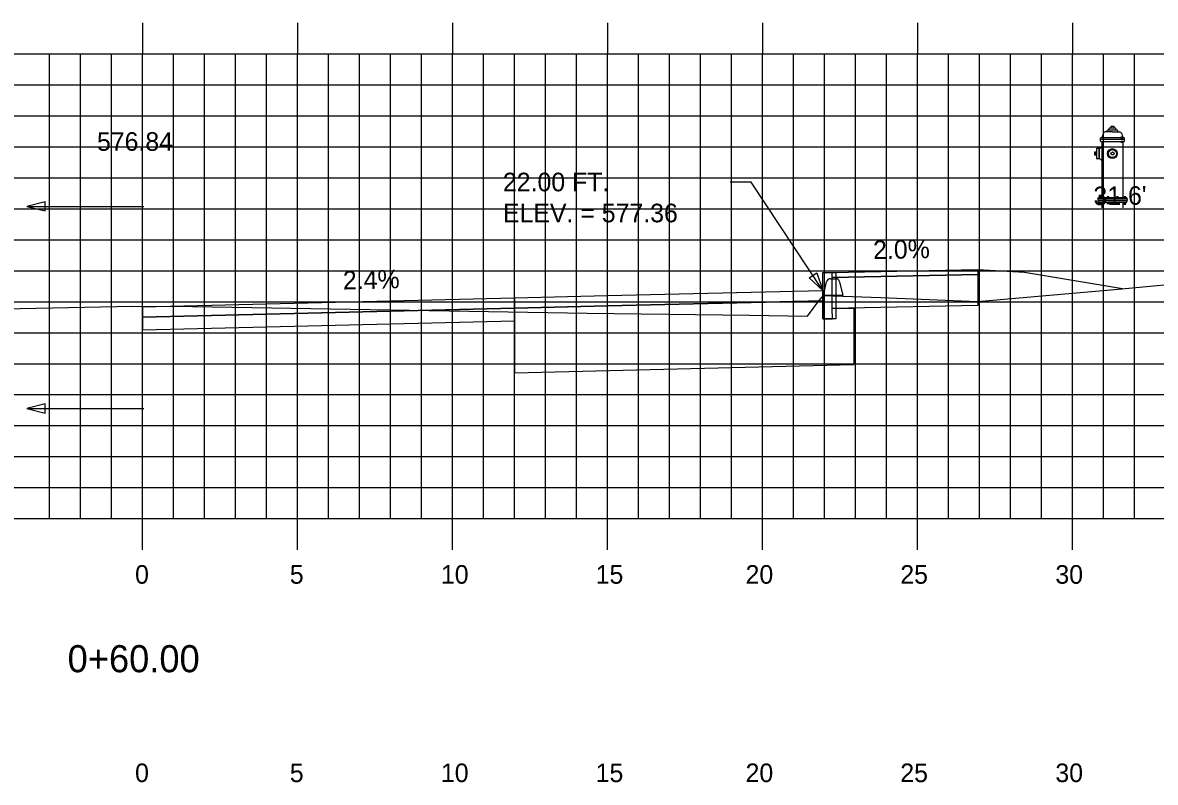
# Model space of a CAD drawing. Extents: x 1048343 to 1048513, y 781387 to 781497.
# Drawn here: x 1048422.25 to 1048458.79, y 781417.87 to 781442.38 of the extents above; entities that cross this region are included whole.
import ezdxf

# ---------------------------------------------------------------- set-up
doc = ezdxf.new("R2010")
doc.units = 0
for name, color, linetype in [('ANNOTATION', 7, 'Continuous'), ('D_Curb_Type1_Lt', 7, 'Continuous'), ('D_Roadway_Berm', 7, 'Continuous'), ('D_Roadway_Centerline', 7, 'Continuous'), ('D_Roadway_Centerline_Text', 7, 'Continuous'), ('D_Roadway_Edge_Shoulder', 7, 'Continuous'), ('D_Roadway_Edge_TW', 7, 'Continuous'), ('D_Roadway_Pavement', 7, 'Continuous'), ('D_Roadway_Sidewalks_Paved', 7, 'Continuous'), ('D_Roadway_SlopeLines', 7, 'Continuous'), ('D_Roadway_SubGrade', 7, 'Continuous'), ('D_Text_Standard', 7, 'Continuous'), ('H_V ANNOTATION', 7, 'Continuous'), ('MAJOR', 7, 'Continuous'), ('MINOR', 7, 'Continuous'), ('S_Curb_Type_3', 7, 'Continuous'), ('S_Roadway_Centerline', 7, 'Continuous'), ('S_Utilities_Hydrant', 7, 'Continuous')]:
    doc.layers.add(name, color=color, linetype=linetype)

msp = doc.modelspace()

# ---------------------------------------------------------------- linework, layer by layer
at = {"layer": 'ANNOTATION'}
for p, q in [((1048422.382, 781436.451), (1048426.157, 781436.451)), ((1048422.382, 781429.933), (1048426.157, 781429.933))]:
    msp.add_line(p, q, dxfattribs=at)
for points in [[(1048422.982, 781436.601), (1048422.382, 781436.451), (1048422.982, 781436.301)], [(1048422.982, 781430.083), (1048422.382, 781429.933), (1048422.982, 781429.783)]]:
    msp.add_lwpolyline(points, close=True, dxfattribs=at)
at = {"layer": 'D_Curb_Type1_Lt'}
msp.add_lwpolyline([(1048448.485, 781434.319), (1048448.485, 781432.819), (1048448.069, 781432.819), (1048448.069, 781434.319)], close=True, dxfattribs=at)
at = {"layer": 'D_Roadway_Berm'}
msp.add_lwpolyline([(1048453.069, 781434.413), (1048454.569, 781434.323)], dxfattribs=at)
at = {"layer": 'D_Roadway_Centerline'}
for p, q in [((1048426.119, 781429.933), (1048426.119, 781436.49)), ((1048426.119, 781433.211), (1048426.119, 781432.461))]:
    msp.add_line(p, q, dxfattribs=at)
at = {"layer": 'D_Roadway_Edge_Shoulder'}
msp.add_lwpolyline([(1048438.119, 781433.498), (1048441.119, 781433.57), (1048448.068, 781433.736), (1048448.068, 781433.403), (1048441.119, 781433.237), (1048438.119, 781433.165)], close=True, dxfattribs=at)
at = {"layer": 'D_Roadway_Edge_TW'}
msp.add_lwpolyline([(1048426.119, 781433.211), (1048438.119, 781433.498), (1048438.119, 781433.165), (1048426.119, 781432.878)], dxfattribs=at)
at = {"layer": 'D_Roadway_Pavement'}
msp.add_lwpolyline([(1048426.119, 781432.878), (1048438.119, 781433.165), (1048438.119, 781432.748), (1048426.119, 781432.461)], dxfattribs=at)
at = {"layer": 'D_Roadway_Sidewalks_Paved'}
msp.add_lwpolyline([(1048448.369, 781434.319), (1048453.069, 781434.413), (1048453.069, 781434.247), (1048448.369, 781434.153)], close=True, dxfattribs=at)
at = {"layer": 'D_Roadway_SlopeLines'}
msp.add_lwpolyline([(1048454.569, 781434.323), (1048457.73, 781433.796)], dxfattribs=at)
at = {"layer": 'D_Roadway_SubGrade'}
for p in [(1048449.068, 781433.167), (1048438.119, 781431.082)]:
    msp.add_line(p, (1048449.068, 781431.343), dxfattribs=at)
msp.add_lwpolyline([(1048448.369, 781434.153), (1048453.069, 781434.247), (1048453.069, 781433.247), (1048448.369, 781433.153)], close=True, dxfattribs=at)
for points in [[(1048438.119, 781431.301), (1048438.119, 781433.165), (1048438.119, 781433.165), (1048441.119, 781433.237), (1048448.068, 781433.403), (1048448.068, 781432.819), (1048448.378, 781432.819), (1048448.369, 781433.153), (1048449.068, 781433.167), (1048449.068, 781431.562)], [(1048438.119, 781433.165), (1048438.119, 781431.082)]]:
    msp.add_lwpolyline(points, dxfattribs=at)
at = {"layer": 'D_Text_Standard'}
msp.add_lwpolyline([(1048448.068, 781433.736), (1048445.751, 781437.236), (1048445.071, 781437.236)], dxfattribs=at)
msp.add_lwpolyline([(1048448.068, 781433.736), (1048447.625, 781434.141), (1048447.868, 781434.302)], close=True, dxfattribs=at)
at = {"layer": 'MAJOR'}
for p, q in [((1048426.119, 781442.377), (1048426.119, 781441.375)), ((1048431.119, 781442.377), (1048431.119, 781441.375)), ((1048436.119, 781442.377), (1048436.119, 781441.375)), ((1048441.119, 781442.377), (1048441.119, 781441.375)), ((1048446.119, 781442.377), (1048446.119, 781441.375)), ((1048451.119, 781442.377), (1048451.119, 781441.375)), ((1048456.119, 781442.377), (1048456.119, 781441.375)), ((1048356.119, 781441.375), (1048496.119, 781441.375)), ((1048356.119, 781441.375), (1048496.119, 781441.375)), ((1048426.119, 781426.375), (1048426.119, 781441.375)), ((1048431.119, 781426.375), (1048431.119, 781441.375)), ((1048436.119, 781426.375), (1048436.119, 781441.375)), ((1048441.119, 781426.375), (1048441.119, 781441.375)), ((1048446.119, 781426.375), (1048446.119, 781441.375)), ((1048451.119, 781426.375), (1048451.119, 781441.375)), ((1048456.119, 781426.375), (1048456.119, 781441.375)), ((1048356.119, 781436.375), (1048496.119, 781436.375)), ((1048356.119, 781431.375), (1048496.119, 781431.375)), ((1048356.119, 781426.375), (1048496.119, 781426.375)), ((1048356.119, 781426.375), (1048496.119, 781426.375)), ((1048426.119, 781425.373), (1048426.119, 781426.375)), ((1048431.119, 781425.373), (1048431.119, 781426.375)), ((1048436.119, 781425.373), (1048436.119, 781426.375)), ((1048441.119, 781425.373), (1048441.119, 781426.375)), ((1048446.119, 781425.373), (1048446.119, 781426.375)), ((1048451.119, 781425.373), (1048451.119, 781426.375)), ((1048456.119, 781425.373), (1048456.119, 781426.375))]:
    msp.add_line(p, q, dxfattribs=at)
at = {"layer": 'MINOR'}
for p, q in [((1048423.119, 781426.375), (1048423.119, 781441.375)), ((1048424.119, 781426.375), (1048424.119, 781441.375)), ((1048425.119, 781426.375), (1048425.119, 781441.375)), ((1048427.119, 781426.375), (1048427.119, 781441.375)), ((1048428.119, 781426.375), (1048428.119, 781441.375)), ((1048429.119, 781426.375), (1048429.119, 781441.375)), ((1048430.119, 781426.375), (1048430.119, 781441.375)), ((1048432.119, 781426.375), (1048432.119, 781441.375)), ((1048433.119, 781426.375), (1048433.119, 781441.375)), ((1048434.119, 781426.375), (1048434.119, 781441.375)), ((1048435.119, 781426.375), (1048435.119, 781441.375)), ((1048437.119, 781426.375), (1048437.119, 781441.375)), ((1048438.119, 781426.375), (1048438.119, 781441.375)), ((1048439.119, 781426.375), (1048439.119, 781441.375)), ((1048440.119, 781426.375), (1048440.119, 781441.375)), ((1048442.119, 781426.375), (1048442.119, 781441.375)), ((1048443.119, 781426.375), (1048443.119, 781441.375)), ((1048444.119, 781426.375), (1048444.119, 781441.375)), ((1048445.119, 781426.375), (1048445.119, 781441.375)), ((1048447.119, 781426.375), (1048447.119, 781441.375)), ((1048448.119, 781426.375), (1048448.119, 781441.375)), ((1048449.119, 781426.375), (1048449.119, 781441.375)), ((1048450.119, 781426.375), (1048450.119, 781441.375)), ((1048452.119, 781426.375), (1048452.119, 781441.375)), ((1048453.119, 781426.375), (1048453.119, 781441.375)), ((1048454.119, 781426.375), (1048454.119, 781441.375)), ((1048455.119, 781426.375), (1048455.119, 781441.375)), ((1048457.119, 781426.375), (1048457.119, 781441.375)), ((1048458.119, 781426.375), (1048458.119, 781441.375)), ((1048356.119, 781440.375), (1048496.119, 781440.375)), ((1048356.119, 781439.375), (1048496.119, 781439.375)), ((1048356.119, 781438.375), (1048496.119, 781438.375)), ((1048356.119, 781437.375), (1048496.119, 781437.375)), ((1048356.119, 781435.375), (1048496.119, 781435.375)), ((1048356.119, 781434.375), (1048496.119, 781434.375)), ((1048356.119, 781433.375), (1048496.119, 781433.375)), ((1048356.119, 781432.375), (1048496.119, 781432.375)), ((1048356.119, 781430.375), (1048496.119, 781430.375)), ((1048356.119, 781429.375), (1048496.119, 781429.375)), ((1048356.119, 781428.375), (1048496.119, 781428.375)), ((1048356.119, 781427.375), (1048496.119, 781427.375))]:
    msp.add_line(p, q, dxfattribs=at)
at = {"layer": 'S_Curb_Type_3'}
for points in [[(1048448.606, 781434.02), (1048448.709, 781433.576), (1048448.084, 781433.576), (1048448.186, 781434.02)], [(1048448.308, 781434.117), (1048448.484, 781434.117)]]:
    msp.add_lwpolyline(points, dxfattribs=at)
for centre, start, end in [((1048448.308, 781433.992), 90, 167.0054), ((1048448.484, 781433.992), 12.9946, 90)]:
    msp.add_arc(centre, 0.125, start, end, dxfattribs=at)
at = {"layer": 'S_Roadway_Centerline'}
msp.add_lwpolyline([(1048397.517, 781432.883), (1048403.278, 781432.868), (1048405.917, 781432.863), (1048409.959, 781432.912), (1048412.069, 781432.919), (1048412.094, 781432.924), (1048422.166, 781433.153), (1048425.802, 781433.232), (1048427.73, 781433.216), (1048440.46, 781433.006), (1048445.704, 781432.939), (1048447.573, 781432.913), (1048447.942, 781433.407), (1048448.084, 781433.576), (1048449.937, 781433.508), (1048453.059, 781433.386), (1048457.596, 781433.784), (1048467.65, 781434.721), (1048470.236, 781434.963), (1048489.197, 781435.231), (1048493.877, 781435.266), (1048494.113, 781435.27), (1048495.01, 781435.311), (1048496.119, 781435.359)], dxfattribs=at)
at = {"layer": 'S_Utilities_Hydrant'}
for p, q in [((1048457.109, 781438.789), (1048457.07, 781438.661)), ((1048457.408, 781438.86), (1048457.177, 781438.86)), ((1048457.255, 781438.916), (1048457.56, 781438.916)), ((1048457.295, 781438.957), (1048457.295, 781438.916)), ((1048457.504, 781438.972), (1048457.312, 781438.972)), ((1048457.408, 781438.86), (1048457.639, 781438.86)), ((1048457.52, 781438.916), (1048457.52, 781438.957)), ((1048457.707, 781438.789), (1048457.746, 781438.661)), ((1048457.014, 781438.645), (1048457.014, 781438.564)), ((1048457.803, 781438.604), (1048457.014, 781438.604)), ((1048457.786, 781438.661), (1048457.03, 781438.661)), ((1048457.07, 781438.548), (1048457.07, 781436.741)), ((1048457.07, 781438.39), (1048457.07, 781438.39)), ((1048457.089, 781438.661), (1048457.089, 781438.678)), ((1048457.089, 781438.524), (1048457.089, 781438.548)), ((1048457.118, 781438.678), (1048457.118, 781438.661)), ((1048457.118, 781438.548), (1048457.118, 781438.524)), ((1048457.699, 781438.678), (1048457.699, 781438.661)), ((1048457.699, 781438.548), (1048457.699, 781438.524)), ((1048457.727, 781438.661), (1048457.727, 781438.678)), ((1048457.727, 781438.524), (1048457.727, 781438.548)), ((1048457.746, 781438.548), (1048457.746, 781436.741)), ((1048456.867, 781438.201), (1048456.867, 781438.199)), ((1048456.867, 781438.199), (1048456.867, 781438.109)), ((1048456.867, 781438.106), (1048456.867, 781438.109)), ((1048456.877, 781438.214), (1048456.877, 781438.093)), ((1048456.882, 781438.215), (1048456.882, 781438.093)), ((1048456.902, 781438.221), (1048456.894, 781438.22)), ((1048456.902, 781438.086), (1048456.894, 781438.088)), ((1048456.902, 781437.996), (1048456.902, 781438.313)), ((1048456.918, 781438.328), (1048456.979, 781438.328)), ((1048456.979, 781438.328), (1048456.979, 781437.979)), ((1048456.986, 781438.318), (1048456.979, 781438.318)), ((1048456.986, 781437.985), (1048456.986, 781438.323)), ((1048456.979, 781437.979), (1048456.917, 781437.979)), ((1048456.986, 781437.99), (1048456.979, 781437.99)), ((1048457.07, 781437.918), (1048457.07, 781437.918)), ((1048457.889, 781436.685), (1048456.938, 781436.685)), ((1048457.889, 781436.629), (1048456.938, 781436.629)), ((1048456.963, 781436.741), (1048457.864, 781436.741)), ((1048457.864, 781436.572), (1048456.963, 781436.572)), ((1048456.998, 781436.759), (1048456.998, 781436.741)), ((1048456.998, 781436.572), (1048456.998, 781436.548)), ((1048457.026, 781436.741), (1048457.026, 781436.759)), ((1048457.026, 781436.548), (1048457.026, 781436.572)), ((1048457.07, 781436.572), (1048457.07, 781436.405)), ((1048457.249, 781436.759), (1048457.249, 781436.741)), ((1048457.249, 781436.572), (1048457.249, 781436.548)), ((1048457.278, 781436.741), (1048457.278, 781436.759)), ((1048457.278, 781436.548), (1048457.278, 781436.572)), ((1048457.55, 781436.759), (1048457.55, 781436.741)), ((1048457.55, 781436.572), (1048457.55, 781436.548)), ((1048457.577, 781436.741), (1048457.577, 781436.759)), ((1048457.577, 781436.548), (1048457.577, 781436.572)), ((1048457.746, 781436.572), (1048457.746, 781436.405)), ((1048457.801, 781436.759), (1048457.801, 781436.741)), ((1048457.801, 781436.572), (1048457.801, 781436.548)), ((1048457.829, 781436.741), (1048457.829, 781436.759)), ((1048457.829, 781436.548), (1048457.829, 781436.572))]:
    msp.add_line(p, q, dxfattribs=at)
for points in [[(1048457.239, 781438.86), (1048457.239, 781438.901), (1048457.24, 781438.901), (1048457.239, 781438.901)], [(1048457.465, 781438.972), (1048457.465, 781439.028), (1048457.352, 781439.028), (1048457.352, 781438.972)], [(1048457.577, 781438.901), (1048457.576, 781438.901), (1048457.577, 781438.901), (1048457.577, 781438.86)], [(1048457.029, 781438.547), (1048457.029, 781438.548), (1048457.787, 781438.548), (1048457.787, 781438.547)], [(1048457.076, 781438.661), (1048457.076, 781438.678), (1048457.079, 781438.682), (1048457.128, 781438.682), (1048457.131, 781438.678), (1048457.131, 781438.661), (1048457.076, 781438.661)], [(1048457.131, 781438.548), (1048457.131, 781438.524), (1048457.128, 781438.52), (1048457.079, 781438.52), (1048457.076, 781438.524), (1048457.076, 781438.548), (1048457.131, 781438.548)], [(1048457.089, 781438.527), (1048457.089, 781438.51), (1048457.118, 781438.51), (1048457.118, 781438.524)], [(1048457.741, 781438.661), (1048457.741, 781438.678), (1048457.737, 781438.682), (1048457.688, 781438.682), (1048457.684, 781438.678), (1048457.684, 781438.661), (1048457.741, 781438.661)], [(1048457.684, 781438.548), (1048457.684, 781438.524), (1048457.688, 781438.52), (1048457.737, 781438.52), (1048457.741, 781438.524), (1048457.741, 781438.548), (1048457.684, 781438.548)], [(1048457.727, 781438.527), (1048457.727, 781438.51), (1048457.699, 781438.51), (1048457.699, 781438.524)], [(1048457.803, 781438.564), (1048457.803, 781438.644), (1048457.803, 781438.645)], [(1048456.867, 781438.199), (1048456.831, 781438.199), (1048456.831, 781438.109), (1048456.867, 781438.109)], [(1048457.44, 781438.11), (1048457.376, 781438.11), (1048457.356, 781438.171), (1048457.408, 781438.209), (1048457.46, 781438.171), (1048457.44, 781438.11)], [(1048457.04, 781436.741), (1048457.04, 781436.759), (1048457.036, 781436.762), (1048456.988, 781436.762), (1048456.984, 781436.759), (1048456.984, 781436.741), (1048457.04, 781436.741)], [(1048456.984, 781436.572), (1048456.984, 781436.548), (1048456.988, 781436.545), (1048457.036, 781436.545), (1048457.04, 781436.548), (1048457.04, 781436.572), (1048456.984, 781436.572)], [(1048457.291, 781436.741), (1048457.291, 781436.759), (1048457.287, 781436.762), (1048457.239, 781436.762), (1048457.235, 781436.759), (1048457.235, 781436.741), (1048457.291, 781436.741)], [(1048457.235, 781436.572), (1048457.235, 781436.548), (1048457.239, 781436.545), (1048457.287, 781436.545), (1048457.291, 781436.548), (1048457.291, 781436.572), (1048457.235, 781436.572)], [(1048457.592, 781436.741), (1048457.592, 781436.759), (1048457.588, 781436.762), (1048457.539, 781436.762), (1048457.535, 781436.759), (1048457.535, 781436.741), (1048457.592, 781436.741)], [(1048457.535, 781436.572), (1048457.535, 781436.548), (1048457.539, 781436.545), (1048457.588, 781436.545), (1048457.592, 781436.548), (1048457.592, 781436.572), (1048457.535, 781436.572)], [(1048457.843, 781436.741), (1048457.843, 781436.759), (1048457.84, 781436.762), (1048457.791, 781436.762), (1048457.787, 781436.759), (1048457.787, 781436.741), (1048457.843, 781436.741)], [(1048457.787, 781436.572), (1048457.787, 781436.548), (1048457.791, 781436.545), (1048457.84, 781436.545), (1048457.843, 781436.548), (1048457.843, 781436.572), (1048457.787, 781436.572)], [(1048457.026, 781436.551), (1048457.026, 781436.535), (1048456.998, 781436.535), (1048456.998, 781436.548)], [(1048457.278, 781436.551), (1048457.278, 781436.535), (1048457.249, 781436.535), (1048457.249, 781436.548)], [(1048457.577, 781436.551), (1048457.577, 781436.535), (1048457.55, 781436.535), (1048457.55, 781436.548)], [(1048457.829, 781436.551), (1048457.829, 781436.535), (1048457.801, 781436.535), (1048457.801, 781436.548)]]:
    msp.add_lwpolyline(points, dxfattribs=at)
for radius in [0.158, 0.128]:
    msp.add_circle((1048457.408, 781438.154), radius, dxfattribs=at)
for centre, radius, start, end in [((1048457.201, 781438.768), 0.0943, 104.4243, 167.4801), ((1048457.258, 781438.897), 0.0191, 96.9921, 168.8028), ((1048457.314, 781438.953), 0.019, 96.6009, 168.4116), ((1048457.502, 781438.953), 0.0191, 11.1972, 83.0079), ((1048457.558, 781438.897), 0.019, 11.5319, 83.3426), ((1048457.615, 781438.768), 0.0943, 12.5199, 75.5757), ((1048456.972, 781438.426), 0.105, 277.4234, 339.5299), ((1048457.033, 781438.641), 0.0191, 96.9921, 168.8028), ((1048457.033, 781438.566), 0.0191, 186.9921, 258.8028), ((1048457.082, 781438.673), 0.00826, 32.9144, 129.4939), ((1048457.082, 781438.528), 0.00826, 230.5064, 327.0859), ((1048457.103, 781438.653), 0.0282, 60.0007, 120.0007), ((1048457.103, 781438.548), 0.0282, 240.0007, 300.0007), ((1048457.124, 781438.673), 0.00826, 50.5064, 147.0859), ((1048457.124, 781438.528), 0.00826, 212.9144, 309.4939), ((1048457.692, 781438.673), 0.00826, 32.9141, 129.4936), ((1048457.692, 781438.528), 0.00826, 230.5061, 327.0856), ((1048457.713, 781438.653), 0.0282, 59.9993, 119.9993), ((1048457.713, 781438.548), 0.0282, 239.9993, 299.9993), ((1048457.734, 781438.673), 0.00826, 50.5061, 147.0856), ((1048457.734, 781438.528), 0.00826, 212.9141, 309.4936), ((1048457.783, 781438.641), 0.0191, 11.1972, 83.0079), ((1048457.783, 781438.566), 0.0191, 281.1972, 353.0079), ((1048456.876, 781438.207), 0.0104, 141.3402, 150.6422), ((1048456.869, 781438.211), 0.00229, 150.6422, 170.5377), ((1048456.944, 781438.199), 0.0782, 170.5377, 171.4341), ((1048456.875, 781438.209), 0.00865, 171.4341, 174.1282), ((1048456.88, 781438.208), 0.013, 174.1282, 177.7182), ((1048456.995, 781438.204), 0.128, 177.7182, 178.8593), ((1048456.952, 781438.205), 0.0857, 178.8593, 179.715), ((1048457.639, 781438.201), 0.772, 179.715, 180), ((1048457.639, 781438.106), 0.772, 180, 180.285), ((1048456.952, 781438.103), 0.0857, 180.285, 181.1407), ((1048456.995, 781438.104), 0.128, 181.1407, 182.2818), ((1048456.875, 781438.098), 0.00865, 185.8718, 188.5659), ((1048456.88, 781438.099), 0.013, 182.2818, 185.8718), ((1048456.944, 781438.109), 0.0782, 188.5659, 189.4623), ((1048456.869, 781438.096), 0.00229, 189.4623, 209.3578), ((1048456.876, 781438.1), 0.0104, 209.3578, 218.6598), ((1048456.825, 781438.248), 0.055, 321.3402, 323.1301), ((1048456.825, 781438.06), 0.055, 36.8699, 38.6598), ((1048456.855, 781438.225), 0.0174, 323.1301, 326.3099), ((1048456.855, 781438.082), 0.0174, 33.6901, 36.8699), ((1048456.871, 781438.215), 0.000947, 97.125, 146.3099), ((1048456.871, 781438.092), 0.000947, 213.6901, 262.875), ((1048456.871, 781438.213), 0.00335, 71.565, 97.125), ((1048456.871, 781438.095), 0.00335, 262.875, 288.435), ((1048456.863, 781438.189), 0.0288, 68.1986, 71.5651), ((1048456.863, 781438.119), 0.0288, 288.4349, 291.8014), ((1048456.868, 781438.202), 0.0144, 63.435, 68.1986), ((1048456.868, 781438.105), 0.0144, 291.8014, 296.565), ((1048456.879, 781438.222), 0.0084, 243.4349, 251.565), ((1048456.879, 781438.085), 0.0084, 108.4349, 116.5651), ((1048456.879, 781438.225), 0.0109, 251.565, 258.6901), ((1048456.879, 781438.083), 0.0109, 101.3099, 108.4349), ((1048456.879, 781438.221), 0.00686, 258.6901, 270), ((1048456.879, 781438.087), 0.00686, 90, 101.3099), ((1048456.879, 781438.231), 0.0173, 270, 277.125), ((1048456.879, 781438.076), 0.0173, 82.875, 90), ((1048456.88, 781438.221), 0.00682, 277.125, 294.444), ((1048456.88, 781438.087), 0.00682, 65.556, 82.875), ((1048456.882, 781438.217), 0.00252, 294.444, 323.1301), ((1048456.882, 781438.09), 0.00252, 36.8699, 65.556), ((1048456.891, 781438.21), 0.00939, 135, 143.1301), ((1048456.891, 781438.098), 0.00939, 216.8699, 225), ((1048456.891, 781438.21), 0.00939, 126.8699, 135), ((1048456.891, 781438.098), 0.00939, 225, 233.1301), ((1048456.888, 781438.214), 0.00357, 105.7372, 126.8699), ((1048456.888, 781438.093), 0.00357, 233.1301, 254.2628), ((1048456.918, 781438.105), 0.117, 102.0619, 105.7372), ((1048456.918, 781438.202), 0.117, 254.2628, 257.9381), ((1048456.92, 781438.309), 0.0191, 96.9921, 168.8028), ((1048456.92, 781437.998), 0.0192, 186.7328, 258.5435), ((1048456.972, 781437.881), 0.105, 20.4701, 82.5766), ((1048457.076, 781436.657), 0.141, 143.1301, 216.8699), ((1048456.991, 781436.754), 0.00826, 32.9141, 129.4936), ((1048457.012, 781436.734), 0.0282, 59.9993, 119.9993), ((1048457.033, 781436.754), 0.00826, 50.5061, 147.0856), ((1048457.242, 781436.754), 0.00826, 32.9141, 129.4936), ((1048457.263, 781436.734), 0.0282, 59.9993, 119.9993), ((1048457.284, 781436.754), 0.00826, 50.5061, 147.0856), ((1048457.543, 781436.754), 0.00826, 32.9141, 129.4936), ((1048457.564, 781436.734), 0.0282, 59.9993, 119.9993), ((1048457.585, 781436.754), 0.00826, 50.5061, 147.0856), ((1048457.794, 781436.754), 0.00826, 32.9141, 129.4936), ((1048457.815, 781436.734), 0.0282, 59.9993, 119.9993), ((1048457.836, 781436.754), 0.00826, 50.5061, 147.0856), ((1048457.751, 781436.657), 0.141, 323.1301, 36.8699), ((1048456.991, 781436.553), 0.00826, 230.5061, 327.0856), ((1048457.012, 781436.572), 0.0282, 239.9993, 299.9993), ((1048457.033, 781436.553), 0.00826, 212.9141, 309.4936), ((1048457.242, 781436.553), 0.00826, 230.5061, 327.0856), ((1048457.263, 781436.572), 0.0282, 239.9993, 299.9993), ((1048457.284, 781436.553), 0.00826, 212.9141, 309.4936), ((1048457.543, 781436.553), 0.00826, 230.5061, 327.0856), ((1048457.564, 781436.572), 0.0282, 239.9993, 299.9993), ((1048457.585, 781436.553), 0.00826, 212.9141, 309.4936), ((1048457.794, 781436.553), 0.00826, 230.5061, 327.0856), ((1048457.815, 781436.572), 0.0282, 239.9993, 299.9993), ((1048457.836, 781436.553), 0.00826, 212.9141, 309.4936)]:
    msp.add_arc(centre, radius, start, end, dxfattribs=at)

# ---------------------------------------------------------------- texts
at = {"layer": 'ANNOTATION'}
for s, rotation, p in [("31.6'", 0.7396, (1048456.801, 781436.484)), ('2.0%', 1.1458, (1048449.694, 781434.746)), ('2.4%', 1.3692, (1048432.59, 781433.766))]:
    msp.add_text(s, height=0.6, rotation=rotation, dxfattribs=at).set_placement(p)
at = {"layer": 'D_Roadway_Centerline'}
for s, p in [('C', (1048426.114, 781433.211)), ('L', (1048426.119, 781433.204))]:
    msp.add_text(s, height=0.0146, dxfattribs=at).set_placement(p)
at = {"layer": 'D_Roadway_Centerline_Text'}
msp.add_text('576.84', height=0.6, dxfattribs=at).set_placement((1048424.648, 781438.243))
at = {"layer": 'D_Text_Standard'}
for s, p in [('22.00 FT.', (1048437.745, 781436.936)), ('ELEV. = 577.36', (1048437.745, 781435.936))]:
    msp.add_text(s, height=0.6, dxfattribs=at).set_placement(p)
at = {"layer": 'H_V ANNOTATION'}
for s, height, p in [('0', 0.6, (1048425.878, 781424.275)), ('5', 0.6, (1048430.87, 781424.275)), ('10', 0.6, (1048435.745, 781424.275)), ('15', 0.6, (1048440.737, 781424.275)), ('20', 0.6, (1048445.573, 781424.275)), ('25', 0.6, (1048450.565, 781424.275)), ('30', 0.6, (1048455.568, 781424.275)), ('0+60.00', 0.875, (1048423.701, 781421.419)), ('0', 0.6, (1048425.878, 781417.875)), ('5', 0.6, (1048430.87, 781417.875)), ('10', 0.6, (1048435.745, 781417.875)), ('15', 0.6, (1048440.737, 781417.875)), ('20', 0.6, (1048445.573, 781417.875)), ('25', 0.6, (1048450.565, 781417.875)), ('30', 0.6, (1048455.568, 781417.875))]:
    msp.add_text(s, height=height, dxfattribs=at).set_placement(p)
at = {"layer": 'S_Roadway_Centerline'}
for s, p in [('L', (1048425.793, 781433.224)), ('C', (1048425.796, 781433.232))]:
    msp.add_text(s, height=0.0146, dxfattribs=at).set_placement(p)

doc.saveas('drawing.dxf')
